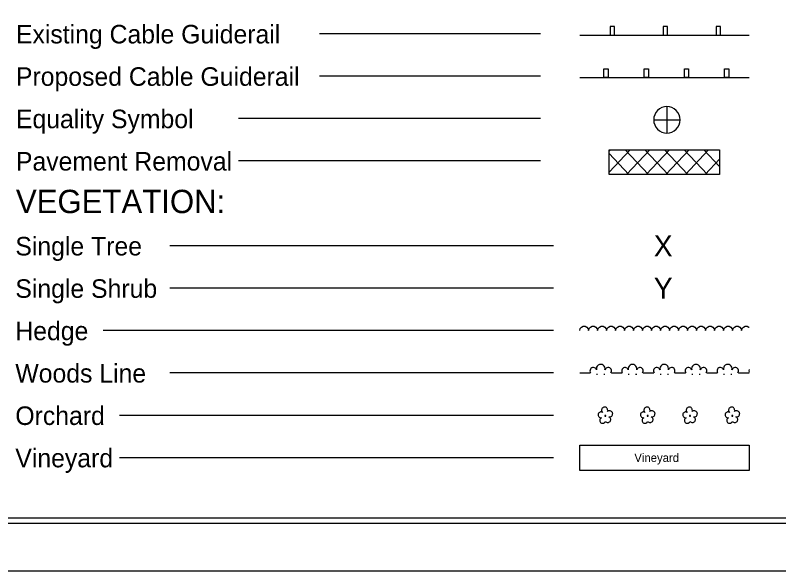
# Model space of a CAD drawing. Extents: x 573855 to 575539, y -53293 to -50956.
# Drawn here: x 574416.8 to 574777.4, y -53293.5 to -53031.3 of the extents above; entities that cross this region are included whole.
import ezdxf

# ---------------------------------------------------------------- set-up
doc = ezdxf.new("R2010")
doc.units = 0
for name, color, linetype in [('Sheet Cutting Line CELL', 7, 'Continuous'), ('Sheet Plot Border Inside CELL', 7, 'Continuous'), ('Sheet Plot Border Outside CELL', 7, 'Continuous'), ('Sheet Symbology CELL', 7, 'Continuous')]:
    doc.layers.add(name, color=color, linetype=linetype)

msp = doc.modelspace()

# ---------------------------------------------------------------- linework, layer by layer
at = {"layer": 'Sheet Cutting Line CELL'}
msp.add_line((573855.41, -53293.48), (575539.41, -53293.48), dxfattribs=at)
at = {"layer": 'Sheet Plot Border Inside CELL'}
msp.add_lwpolyline([(573868.41, -53271.03), (575534.91, -53271.03), (575534.91, -52215.93), (573868.41, -52215.93)], close=True, dxfattribs=at)
at = {"layer": 'Sheet Plot Border Outside CELL'}
msp.add_lwpolyline([(573855.41, -53293.48), (575539.41, -53293.48), (575539.41, -52193.48), (573855.41, -52193.48)], close=True, dxfattribs=at)
at = {"layer": 'Sheet Symbology CELL'}
for p, q in [((574664.89, -53040.09), (574560.59, -53040.09)), ((574683.42, -53040.67), (574763.42, -53040.67)), ((574664.89, -53060.09), (574560.59, -53060.09)), ((574683.42, -53060.67), (574763.42, -53060.67)), ((574724.64, -53074.43), (574724.64, -53080.68)), ((574664.89, -53080.09), (574522.26, -53080.09)), ((574718.39, -53080.68), (574724.64, -53080.68)), ((574724.64, -53080.68), (574724.64, -53086.93)), ((574724.64, -53080.68), (574730.89, -53080.68)), ((574697.37, -53094.81), (574749.47, -53094.81)), ((574697.37, -53106.51), (574697.37, -53094.81)), ((574697.37, -53095.41), (574697.92, -53094.81)), ((574697.37, -53105.36), (574707.22, -53094.81)), ((574706.62, -53106.51), (574697.37, -53096.61)), ((574715.92, -53106.51), (574704.92, -53094.81)), ((574705.52, -53106.51), (574716.52, -53094.81)), ((574725.17, -53106.51), (574714.22, -53094.81)), ((574714.77, -53106.51), (574725.82, -53094.81)), ((574734.47, -53106.51), (574723.47, -53094.81)), ((574724.07, -53106.51), (574735.07, -53094.81)), ((574743.77, -53106.51), (574732.72, -53094.81)), ((574733.37, -53106.51), (574744.32, -53094.81)), ((574749.47, -53102.76), (574742.02, -53094.81)), ((574749.47, -53094.81), (574749.47, -53106.51)), ((574664.89, -53100.09), (574522.26, -53100.09)), ((574742.62, -53106.51), (574749.47, -53099.21)), ((574749.47, -53106.51), (574697.37, -53106.51)), ((574671.03, -53140.16), (574489.9, -53140.16)), ((574671.03, -53160.16), (574489.9, -53160.16)), ((574671.03, -53180.16), (574458.34, -53180.16)), ((574683.42, -53180.16), (574683.72, -53179.21)), ((574683.72, -53179.21), (574684.32, -53178.56)), ((574684.32, -53178.56), (574685.12, -53178.11)), ((574685.12, -53178.11), (574686.07, -53178.11)), ((574686.07, -53178.11), (574686.87, -53178.61)), ((574686.87, -53178.61), (574687.42, -53179.26)), ((574687.42, -53179.26), (574687.62, -53180.11)), ((574687.67, -53180.16), (574687.97, -53179.21)), ((574687.97, -53179.21), (574688.57, -53178.56)), ((574688.57, -53178.56), (574689.37, -53178.11)), ((574689.37, -53178.11), (574690.32, -53178.11)), ((574690.32, -53178.11), (574691.12, -53178.61)), ((574691.12, -53178.61), (574691.67, -53179.26)), ((574691.67, -53179.26), (574691.87, -53180.11)), ((574691.92, -53180.16), (574692.22, -53179.21)), ((574692.22, -53179.21), (574692.82, -53178.56)), ((574692.82, -53178.56), (574693.62, -53178.11)), ((574693.62, -53178.11), (574694.57, -53178.11)), ((574694.57, -53178.11), (574695.37, -53178.61)), ((574695.37, -53178.61), (574695.92, -53179.26)), ((574695.92, -53179.26), (574696.12, -53180.11)), ((574696.17, -53180.16), (574696.47, -53179.21)), ((574696.47, -53179.21), (574697.07, -53178.56)), ((574697.07, -53178.56), (574697.87, -53178.11)), ((574697.87, -53178.11), (574698.82, -53178.11)), ((574698.82, -53178.11), (574699.62, -53178.61)), ((574699.62, -53178.61), (574700.17, -53179.26)), ((574700.17, -53179.26), (574700.37, -53180.11)), ((574700.42, -53180.16), (574700.72, -53179.21)), ((574700.72, -53179.21), (574701.32, -53178.56)), ((574701.32, -53178.56), (574702.12, -53178.11)), ((574702.12, -53178.11), (574703.07, -53178.11)), ((574703.07, -53178.11), (574703.87, -53178.61)), ((574703.87, -53178.61), (574704.42, -53179.26)), ((574704.42, -53179.26), (574704.62, -53180.11)), ((574704.67, -53180.16), (574704.97, -53179.21)), ((574704.97, -53179.21), (574705.57, -53178.56)), ((574705.57, -53178.56), (574706.37, -53178.11)), ((574706.37, -53178.11), (574707.32, -53178.11)), ((574707.32, -53178.11), (574708.12, -53178.61)), ((574708.12, -53178.61), (574708.67, -53179.26)), ((574708.67, -53179.26), (574708.87, -53180.11)), ((574708.92, -53180.16), (574709.22, -53179.21)), ((574709.22, -53179.21), (574709.82, -53178.56)), ((574709.82, -53178.56), (574710.62, -53178.11)), ((574710.62, -53178.11), (574711.57, -53178.11)), ((574711.57, -53178.11), (574712.37, -53178.61)), ((574712.37, -53178.61), (574712.92, -53179.26)), ((574712.92, -53179.26), (574713.12, -53180.11)), ((574713.17, -53180.16), (574713.47, -53179.21)), ((574713.47, -53179.21), (574714.07, -53178.56)), ((574714.07, -53178.56), (574714.87, -53178.11)), ((574714.87, -53178.11), (574715.82, -53178.11)), ((574715.82, -53178.11), (574716.62, -53178.61)), ((574716.62, -53178.61), (574717.17, -53179.26)), ((574717.17, -53179.26), (574717.37, -53180.11)), ((574717.42, -53180.16), (574717.72, -53179.21)), ((574717.72, -53179.21), (574718.32, -53178.56)), ((574718.32, -53178.56), (574719.12, -53178.11)), ((574719.12, -53178.11), (574720.07, -53178.11)), ((574720.07, -53178.11), (574720.87, -53178.61)), ((574720.87, -53178.61), (574721.42, -53179.26)), ((574721.42, -53179.26), (574721.62, -53180.11)), ((574721.67, -53180.16), (574721.97, -53179.21)), ((574721.97, -53179.21), (574722.57, -53178.56)), ((574722.57, -53178.56), (574723.37, -53178.11)), ((574723.37, -53178.11), (574724.32, -53178.11)), ((574724.32, -53178.11), (574725.12, -53178.61)), ((574725.12, -53178.61), (574725.67, -53179.26)), ((574725.67, -53179.26), (574725.87, -53180.11)), ((574725.92, -53180.16), (574726.22, -53179.21)), ((574726.22, -53179.21), (574726.82, -53178.56)), ((574726.82, -53178.56), (574727.62, -53178.11)), ((574727.62, -53178.11), (574728.57, -53178.11)), ((574728.57, -53178.11), (574729.37, -53178.61)), ((574729.37, -53178.61), (574729.92, -53179.26)), ((574729.92, -53179.26), (574730.12, -53180.11)), ((574730.17, -53180.16), (574730.47, -53179.21)), ((574730.47, -53179.21), (574731.07, -53178.56)), ((574731.07, -53178.56), (574731.87, -53178.11)), ((574731.87, -53178.11), (574732.82, -53178.11)), ((574732.82, -53178.11), (574733.62, -53178.61)), ((574733.62, -53178.61), (574734.17, -53179.26)), ((574734.17, -53179.26), (574734.37, -53180.11)), ((574734.42, -53180.16), (574734.72, -53179.21)), ((574734.72, -53179.21), (574735.32, -53178.56)), ((574735.32, -53178.56), (574736.12, -53178.11)), ((574736.12, -53178.11), (574737.07, -53178.11)), ((574737.07, -53178.11), (574737.87, -53178.61)), ((574737.87, -53178.61), (574738.42, -53179.26)), ((574738.42, -53179.26), (574738.62, -53180.11)), ((574738.67, -53180.16), (574738.97, -53179.21)), ((574738.97, -53179.21), (574739.57, -53178.56)), ((574739.57, -53178.56), (574740.37, -53178.11)), ((574740.37, -53178.11), (574741.32, -53178.11)), ((574741.32, -53178.11), (574742.12, -53178.61)), ((574742.12, -53178.61), (574742.67, -53179.26)), ((574742.67, -53179.26), (574742.87, -53180.11)), ((574742.92, -53180.16), (574743.22, -53179.21)), ((574743.22, -53179.21), (574743.82, -53178.56)), ((574743.82, -53178.56), (574744.62, -53178.11)), ((574744.62, -53178.11), (574745.57, -53178.11)), ((574745.57, -53178.11), (574746.37, -53178.61)), ((574746.37, -53178.61), (574746.92, -53179.26)), ((574746.92, -53179.26), (574747.12, -53180.11)), ((574747.17, -53180.16), (574747.47, -53179.21)), ((574747.47, -53179.21), (574748.07, -53178.56)), ((574748.07, -53178.56), (574748.87, -53178.11)), ((574748.87, -53178.11), (574749.82, -53178.11)), ((574749.82, -53178.11), (574750.62, -53178.61)), ((574750.62, -53178.61), (574751.17, -53179.26)), ((574751.17, -53179.26), (574751.37, -53180.11)), ((574751.42, -53180.16), (574751.72, -53179.21)), ((574751.72, -53179.21), (574752.32, -53178.56)), ((574752.32, -53178.56), (574753.12, -53178.11)), ((574753.12, -53178.11), (574754.07, -53178.11)), ((574754.07, -53178.11), (574754.87, -53178.61)), ((574754.87, -53178.61), (574755.42, -53179.26)), ((574755.42, -53179.26), (574755.62, -53180.11)), ((574755.67, -53180.16), (574755.97, -53179.21)), ((574755.97, -53179.21), (574756.57, -53178.56)), ((574756.57, -53178.56), (574757.37, -53178.11)), ((574757.37, -53178.11), (574758.32, -53178.11)), ((574758.32, -53178.11), (574759.12, -53178.61)), ((574759.12, -53178.61), (574759.67, -53179.26)), ((574759.67, -53179.26), (574759.87, -53180.11)), ((574759.92, -53180.16), (574760.22, -53179.21)), ((574760.22, -53179.21), (574760.82, -53178.56)), ((574760.82, -53178.56), (574761.62, -53178.11)), ((574761.62, -53178.11), (574762.57, -53178.11)), ((574762.57, -53178.11), (574763.37, -53178.61)), ((574763.37, -53178.61), (574763.42, -53178.66)), ((574671.03, -53200.16), (574489.9, -53200.16)), ((574683.42, -53200.16), (574688.42, -53200.16)), ((574691.37, -53200.66), (574691.87, -53200.66)), ((574694.87, -53200.66), (574695.37, -53200.66)), ((574698.42, -53200.16), (574703.42, -53200.16)), ((574706.37, -53200.66), (574706.87, -53200.66)), ((574709.87, -53200.66), (574710.37, -53200.66)), ((574713.42, -53200.16), (574718.42, -53200.16)), ((574721.37, -53200.66), (574721.87, -53200.66)), ((574724.87, -53200.66), (574725.37, -53200.66)), ((574728.42, -53200.16), (574733.42, -53200.16)), ((574736.37, -53200.66), (574736.87, -53200.66)), ((574739.87, -53200.66), (574740.37, -53200.66)), ((574743.42, -53200.16), (574748.42, -53200.16)), ((574751.37, -53200.66), (574751.87, -53200.66)), ((574754.87, -53200.66), (574755.37, -53200.66)), ((574758.42, -53200.16), (574763.42, -53200.16)), ((574671.03, -53220.16), (574466.09, -53220.16)), ((574671.03, -53240.16), (574466.09, -53240.16))]:
    msp.add_line(p, q, dxfattribs=at)
for points in [[(575522.41, -52218.48), (574022.41, -52218.48), (574022.41, -53268.48), (575522.41, -53268.48)], [(574697.89, -53040.67), (574699.89, -53040.67), (574699.89, -53036.67), (574697.89, -53036.67)], [(574722.89, -53040.67), (574724.89, -53040.67), (574724.89, -53036.67), (574722.89, -53036.67)], [(574747.89, -53040.67), (574749.89, -53040.67), (574749.89, -53036.67), (574747.89, -53036.67)], [(574694.88, -53056.67), (574696.88, -53056.67), (574696.88, -53060.67), (574694.88, -53060.67)], [(574713.88, -53056.67), (574715.88, -53056.67), (574715.88, -53060.67), (574713.88, -53060.67)], [(574732.88, -53056.67), (574734.88, -53056.67), (574734.88, -53060.67), (574732.88, -53060.67)], [(574751.88, -53056.67), (574753.88, -53056.67), (574753.88, -53060.67), (574751.88, -53060.67)]]:
    msp.add_lwpolyline(points, close=True, dxfattribs=at)
for points in [[(574696.47, -53218.41), (574696.62, -53218.11), (574696.67, -53217.81), (574696.62, -53217.51), (574696.57, -53217.21), (574696.42, -53216.96), (574696.27, -53216.71), (574696.02, -53216.51), (574695.77, -53216.36), (574695.42, -53216.26), (574695.17, -53216.26), (574694.87, -53216.31), (574694.57, -53216.41), (574694.32, -53216.56), (574694.07, -53216.76), (574693.92, -53217.06), (574693.82, -53217.31), (574693.77, -53217.61), (574693.77, -53217.91), (574693.82, -53218.21), (574693.97, -53218.46), (574694.17, -53218.76), (574693.92, -53218.61), (574693.62, -53218.56), (574693.32, -53218.56), (574693.07, -53218.66), (574692.82, -53218.76), (574692.57, -53218.96), (574692.37, -53219.16), (574692.22, -53219.41), (574692.17, -53219.66), (574692.12, -53220.01), (574692.17, -53220.26), (574692.27, -53220.51), (574692.47, -53220.76), (574692.62, -53220.96), (574692.87, -53221.11), (574693.17, -53221.26), (574693.42, -53221.31), (574693.72, -53221.31), (574693.47, -53221.41), (574693.22, -53221.61), (574693.07, -53221.81), (574692.97, -53222.11), (574692.87, -53222.41), (574692.87, -53222.66), (574692.92, -53222.96), (574693.07, -53223.21), (574693.22, -53223.46), (574693.42, -53223.66), (574693.67, -53223.81), (574693.92, -53223.91), (574694.22, -53223.91), (574694.52, -53223.91), (574694.77, -53223.86), (574695.02, -53223.66), (574695.27, -53223.51), (574695.52, -53223.06)], [(574716.47, -53218.41), (574716.62, -53218.11), (574716.67, -53217.81), (574716.62, -53217.51), (574716.57, -53217.21), (574716.42, -53216.96), (574716.27, -53216.71), (574716.02, -53216.51), (574715.77, -53216.36), (574715.42, -53216.26), (574715.17, -53216.26), (574714.87, -53216.31), (574714.57, -53216.41), (574714.32, -53216.56), (574714.07, -53216.76), (574713.92, -53217.06), (574713.82, -53217.31), (574713.77, -53217.61), (574713.77, -53217.91), (574713.82, -53218.21), (574713.97, -53218.46), (574714.17, -53218.76), (574713.92, -53218.61), (574713.62, -53218.56), (574713.32, -53218.56), (574713.07, -53218.66), (574712.82, -53218.76), (574712.57, -53218.96), (574712.37, -53219.16), (574712.22, -53219.41), (574712.17, -53219.66), (574712.12, -53220.01), (574712.17, -53220.26), (574712.27, -53220.51), (574712.47, -53220.76), (574712.62, -53220.96), (574712.87, -53221.11), (574713.17, -53221.26), (574713.42, -53221.31), (574713.72, -53221.31), (574713.47, -53221.41), (574713.22, -53221.61), (574713.07, -53221.81), (574712.97, -53222.11), (574712.87, -53222.41), (574712.87, -53222.66), (574712.92, -53222.96), (574713.07, -53223.21), (574713.22, -53223.46), (574713.42, -53223.66), (574713.67, -53223.81), (574713.92, -53223.91), (574714.22, -53223.91), (574714.52, -53223.91), (574714.77, -53223.86), (574715.02, -53223.66), (574715.27, -53223.51), (574715.52, -53223.06)], [(574736.47, -53218.41), (574736.62, -53218.11), (574736.67, -53217.81), (574736.62, -53217.51), (574736.57, -53217.21), (574736.42, -53216.96), (574736.27, -53216.71), (574736.02, -53216.51), (574735.77, -53216.36), (574735.42, -53216.26), (574735.17, -53216.26), (574734.87, -53216.31), (574734.57, -53216.41), (574734.32, -53216.56), (574734.07, -53216.76), (574733.92, -53217.06), (574733.82, -53217.31), (574733.77, -53217.61), (574733.77, -53217.91), (574733.82, -53218.21), (574733.97, -53218.46), (574734.17, -53218.76), (574733.92, -53218.61), (574733.62, -53218.56), (574733.32, -53218.56), (574733.07, -53218.66), (574732.82, -53218.76), (574732.57, -53218.96), (574732.37, -53219.16), (574732.22, -53219.41), (574732.17, -53219.66), (574732.12, -53220.01), (574732.17, -53220.26), (574732.27, -53220.51), (574732.47, -53220.76), (574732.62, -53220.96), (574732.87, -53221.11), (574733.17, -53221.26), (574733.42, -53221.31), (574733.72, -53221.31), (574733.47, -53221.41), (574733.22, -53221.61), (574733.07, -53221.81), (574732.97, -53222.11), (574732.87, -53222.41), (574732.87, -53222.66), (574732.92, -53222.96), (574733.07, -53223.21), (574733.22, -53223.46), (574733.42, -53223.66), (574733.67, -53223.81), (574733.92, -53223.91), (574734.22, -53223.91), (574734.52, -53223.91), (574734.77, -53223.86), (574735.02, -53223.66), (574735.27, -53223.51), (574735.52, -53223.06)], [(574756.47, -53218.41), (574756.62, -53218.11), (574756.67, -53217.81), (574756.62, -53217.51), (574756.57, -53217.21), (574756.42, -53216.96), (574756.27, -53216.71), (574756.02, -53216.51), (574755.77, -53216.36), (574755.42, -53216.26), (574755.17, -53216.26), (574754.87, -53216.31), (574754.57, -53216.41), (574754.32, -53216.56), (574754.07, -53216.76), (574753.92, -53217.06), (574753.82, -53217.31), (574753.77, -53217.61), (574753.77, -53217.91), (574753.82, -53218.21), (574753.97, -53218.46), (574754.17, -53218.76), (574753.92, -53218.61), (574753.62, -53218.56), (574753.32, -53218.56), (574753.07, -53218.66), (574752.82, -53218.76), (574752.57, -53218.96), (574752.37, -53219.16), (574752.22, -53219.41), (574752.17, -53219.66), (574752.12, -53220.01), (574752.17, -53220.26), (574752.27, -53220.51), (574752.47, -53220.76), (574752.62, -53220.96), (574752.87, -53221.11), (574753.17, -53221.26), (574753.42, -53221.31), (574753.72, -53221.31), (574753.47, -53221.41), (574753.22, -53221.61), (574753.07, -53221.81), (574752.97, -53222.11), (574752.87, -53222.41), (574752.87, -53222.66), (574752.92, -53222.96), (574753.07, -53223.21), (574753.22, -53223.46), (574753.42, -53223.66), (574753.67, -53223.81), (574753.92, -53223.91), (574754.22, -53223.91), (574754.52, -53223.91), (574754.77, -53223.86), (574755.02, -53223.66), (574755.27, -53223.51), (574755.52, -53223.06)], [(574695.52, -53223.06), (574696.12, -53223.41), (574696.42, -53223.51), (574696.72, -53223.56), (574697.02, -53223.51), (574697.27, -53223.41), (574697.52, -53223.26), (574697.77, -53223.06), (574697.92, -53222.81), (574698.02, -53222.56), (574698.12, -53222.26), (574698.07, -53221.96), (574698.02, -53221.66), (574697.82, -53221.36), (574697.67, -53221.16), (574697.42, -53221.01), (574697.12, -53220.86), (574697.42, -53220.91), (574697.77, -53220.91), (574698.02, -53220.81), (574698.32, -53220.66), (574698.57, -53220.51), (574698.77, -53220.26), (574698.92, -53219.96), (574698.97, -53219.66), (574699.02, -53219.36), (574698.97, -53219.06), (574698.87, -53218.76), (574698.67, -53218.51), (574698.42, -53218.26), (574698.17, -53218.11), (574697.87, -53218.01), (574697.57, -53217.96), (574697.27, -53217.96), (574696.97, -53218.06), (574696.72, -53218.21), (574696.47, -53218.41)], [(574715.52, -53223.06), (574716.12, -53223.41), (574716.42, -53223.51), (574716.72, -53223.56), (574717.02, -53223.51), (574717.27, -53223.41), (574717.52, -53223.26), (574717.77, -53223.06), (574717.92, -53222.81), (574718.02, -53222.56), (574718.12, -53222.26), (574718.07, -53221.96), (574718.02, -53221.66), (574717.82, -53221.36), (574717.67, -53221.16), (574717.42, -53221.01), (574717.12, -53220.86), (574717.42, -53220.91), (574717.77, -53220.91), (574718.02, -53220.81), (574718.32, -53220.66), (574718.57, -53220.51), (574718.77, -53220.26), (574718.92, -53219.96), (574718.97, -53219.66), (574719.02, -53219.36), (574718.97, -53219.06), (574718.87, -53218.76), (574718.67, -53218.51), (574718.42, -53218.26), (574718.17, -53218.11), (574717.87, -53218.01), (574717.57, -53217.96), (574717.27, -53217.96), (574716.97, -53218.06), (574716.72, -53218.21), (574716.47, -53218.41)], [(574735.52, -53223.06), (574736.12, -53223.41), (574736.42, -53223.51), (574736.72, -53223.56), (574737.02, -53223.51), (574737.27, -53223.41), (574737.52, -53223.26), (574737.77, -53223.06), (574737.92, -53222.81), (574738.02, -53222.56), (574738.12, -53222.26), (574738.07, -53221.96), (574738.02, -53221.66), (574737.82, -53221.36), (574737.67, -53221.16), (574737.42, -53221.01), (574737.12, -53220.86), (574737.42, -53220.91), (574737.77, -53220.91), (574738.02, -53220.81), (574738.32, -53220.66), (574738.57, -53220.51), (574738.77, -53220.26), (574738.92, -53219.96), (574738.97, -53219.66), (574739.02, -53219.36), (574738.97, -53219.06), (574738.87, -53218.76), (574738.67, -53218.51), (574738.42, -53218.26), (574738.17, -53218.11), (574737.87, -53218.01), (574737.57, -53217.96), (574737.27, -53217.96), (574736.97, -53218.06), (574736.72, -53218.21), (574736.47, -53218.41)], [(574755.52, -53223.06), (574756.12, -53223.41), (574756.42, -53223.51), (574756.72, -53223.56), (574757.02, -53223.51), (574757.27, -53223.41), (574757.52, -53223.26), (574757.77, -53223.06), (574757.92, -53222.81), (574758.02, -53222.56), (574758.12, -53222.26), (574758.07, -53221.96), (574758.02, -53221.66), (574757.82, -53221.36), (574757.67, -53221.16), (574757.42, -53221.01), (574757.12, -53220.86), (574757.42, -53220.91), (574757.77, -53220.91), (574758.02, -53220.81), (574758.32, -53220.66), (574758.57, -53220.51), (574758.77, -53220.26), (574758.92, -53219.96), (574758.97, -53219.66), (574759.02, -53219.36), (574758.97, -53219.06), (574758.87, -53218.76), (574758.67, -53218.51), (574758.42, -53218.26), (574758.17, -53218.11), (574757.87, -53218.01), (574757.57, -53217.96), (574757.27, -53217.96), (574756.97, -53218.06), (574756.72, -53218.21), (574756.47, -53218.41)], [(574695.62, -53220.16), (574695.47, -53220.16), (574695.37, -53220.21), (574695.27, -53220.26), (574695.27, -53220.41), (574695.27, -53220.51), (574695.37, -53220.61), (574695.52, -53220.61), (574695.62, -53220.61), (574695.72, -53220.51), (574695.77, -53220.36), (574695.72, -53220.26), (574695.62, -53220.16)], [(574715.62, -53220.16), (574715.47, -53220.16), (574715.37, -53220.21), (574715.27, -53220.26), (574715.27, -53220.41), (574715.27, -53220.51), (574715.37, -53220.61), (574715.52, -53220.61), (574715.62, -53220.61), (574715.72, -53220.51), (574715.77, -53220.36), (574715.72, -53220.26), (574715.62, -53220.16)], [(574735.62, -53220.16), (574735.47, -53220.16), (574735.37, -53220.21), (574735.27, -53220.26), (574735.27, -53220.41), (574735.27, -53220.51), (574735.37, -53220.61), (574735.52, -53220.61), (574735.62, -53220.61), (574735.72, -53220.51), (574735.77, -53220.36), (574735.72, -53220.26), (574735.62, -53220.16)], [(574755.62, -53220.16), (574755.47, -53220.16), (574755.37, -53220.21), (574755.27, -53220.26), (574755.27, -53220.41), (574755.27, -53220.51), (574755.37, -53220.61), (574755.52, -53220.61), (574755.62, -53220.61), (574755.72, -53220.51), (574755.77, -53220.36), (574755.72, -53220.26), (574755.62, -53220.16)], [(574683.42, -53234.16), (574763.42, -53234.16), (574763.42, -53246.16), (574683.42, -53246.16), (574683.42, -53234.16)]]:
    msp.add_lwpolyline(points, dxfattribs=at)
for centre, radius, start, end in [((574724.64, -53080.68), 6.25, 89.9944, 179.9989), ((574724.64, -53080.68), 6.25, 359.9944, 89.9989), ((574724.64, -53080.68), 6.25, 179.9944, 269.9989), ((574724.64, -53080.68), 6.25, 269.9944, 359.9989), ((574689.87, -53199.15), 1.58, 18.435, 219.2315), ((574693.37, -53198.15), 2.06, 345.9638, 194.0362), ((574696.87, -53199.15), 1.58, 320.7685, 161.5651), ((574704.87, -53199.15), 1.58, 18.435, 219.2315), ((574708.37, -53198.15), 2.06, 345.9638, 194.0362), ((574711.87, -53199.15), 1.58, 320.7685, 161.5651), ((574719.87, -53199.15), 1.58, 18.435, 219.2315), ((574723.37, -53198.15), 2.06, 345.9638, 194.0362), ((574726.87, -53199.15), 1.58, 320.7685, 161.5651), ((574734.87, -53199.15), 1.58, 18.435, 219.2315), ((574738.37, -53198.15), 2.06, 345.9638, 194.0362), ((574741.87, -53199.15), 1.58, 320.7685, 161.5651), ((574749.87, -53199.15), 1.58, 18.435, 219.2315), ((574753.37, -53198.15), 2.06, 345.9638, 194.0362), ((574756.87, -53199.15), 1.58, 320.7685, 161.5651), ((574764.87, -53199.15), 1.58, 156.251, 203.749)]:
    msp.add_arc(centre, radius, start, end, dxfattribs=at)

# ---------------------------------------------------------------- texts
for s, height, p in [('Existing Cable Guiderail', 8.75, (574417.15, -53044.63)), ('Proposed Cable Guiderail', 8.75, (574417.15, -53064.63)), ('Equality Symbol', 8.75, (574417.15, -53084.63)), ('Pavement Removal', 8.75, (574417.15, -53104.63)), ('VEGETATION:', 11, (574417.14, -53124.71)), ('Single Tree', 8.75, (574416.86, -53144.69)), ('X', 10, (574718.42, -53145.16)), ('Single Shrub', 8.75, (574416.86, -53164.69)), ('Y', 10, (574718.42, -53165.16)), ('Hedge', 8.75, (574416.86, -53184.69)), ('Woods Line', 8.75, (574416.86, -53204.69)), ('Orchard', 8.75, (574416.86, -53224.69)), ('Vineyard', 8.75, (574416.86, -53244.69))]:
    msp.add_text(s, height=height, dxfattribs=at).set_placement(p)
msp.add_text('Vineyard', height=4, rotation=0, dxfattribs=at).set_placement((574709.24, -53242.16))

doc.saveas('drawing.dxf')
